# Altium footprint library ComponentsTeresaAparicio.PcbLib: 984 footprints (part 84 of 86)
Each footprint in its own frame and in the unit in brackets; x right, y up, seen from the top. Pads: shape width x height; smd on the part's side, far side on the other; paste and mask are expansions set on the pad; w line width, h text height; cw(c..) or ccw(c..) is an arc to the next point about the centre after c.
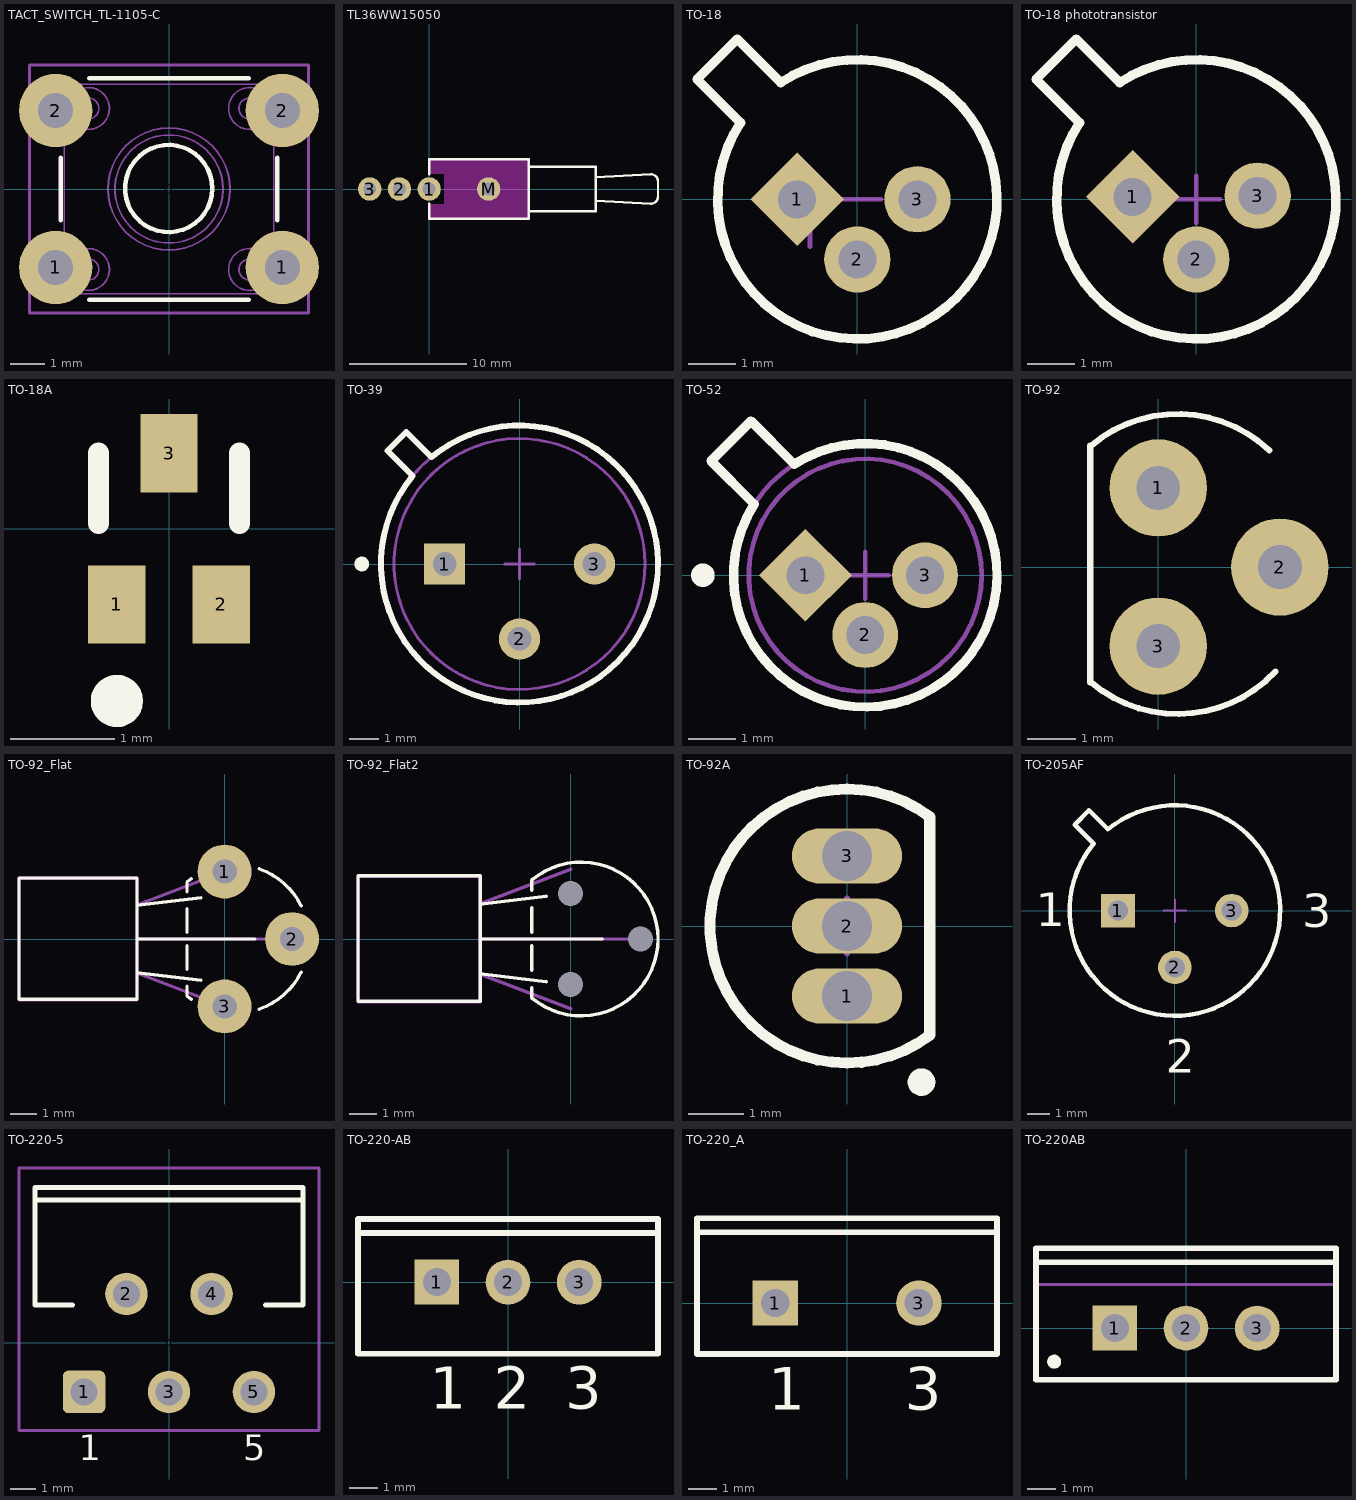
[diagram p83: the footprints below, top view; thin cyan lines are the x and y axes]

## TACT_SWITCH_TL-1105-C [mm] "E-Switch TL1105 series tact switch 8.0mm stem height"
height 8
pads (5):
  round 0.508 on Mech14: 0(0,0)
  round 2.1 hole 1: 1(-3.25,-2.25) 1(3.25,-2.25) 2(-3.25,2.25) 2(3.25,2.25)
Top Overlay:
  circle w0.127: c-0.011,0.014 r1.25
  lines w0.127: -3.1,-0.9 -3.1,0.9 ; -2.286,-3.175 2.286,-3.175 ; -2.286,3.175 2.286,3.175 ; 3.1,-0.9 3.1,0.9
Mechanical 13:
  circle w0.05: c-2.309,-2.309 r0.6
  circle w0.05: c2.309,-2.309 r0.6
  circle w0.05: c-2.309,2.309 r0.6
  circle w0.05: c2.309,2.309 r0.6
  circle w0.05: c2.307,-2.308 r0.3
  circle w0.05: c-2.31,-2.308 r0.3
  circle w0.05: c2.307,2.309 r0.3
  circle w0.05: c-2.31,2.309 r0.3
  circle w0.05: c0,0 r1.75
  circle w0.05: c0,0 r1.55
  lines w0.05: -3.886,-2.65 -3.886,-1.85 ; -3.886,1.85 -3.886,2.65 ; -3.3,-2.65 -3.3,-1.85 ; -3.3,1.85 -3.3,2.65 ; -3.15,-2.65 -3.15,-1.85 ; -3.15,1.85 -3.15,2.65 ; -3,-2.65 -3.95,-2.65 -3.95,-1.85 -3,-1.85 ; -3,1.85 -3.95,1.85 -3.95,2.65 -3,2.65 ; -2.561,-2.853 ccw(c-2.309,-2.309) -2.538,-2.863 ; -2.561,1.764 ccw(c-2.309,2.309) -2.538,1.754 ; 2.056,-2.853 ccw(c2.309,-2.309) 2.079,-2.863 ; 2.056,1.764 ccw(c2.309,2.309) 2.079,1.754 ; 3,-2.65 3.95,-2.65 3.95,-1.85 3,-1.85 ; 3,1.85 3.95,1.85 3.95,2.65 3,2.65 ; 3.15,-2.65 3.15,-1.85 ; 3.15,1.85 3.15,2.65 ; 3.3,-2.65 3.3,-1.85 ; 3.3,1.85 3.3,2.65 ; 3.886,-2.65 3.886,-1.85 ; 3.886,1.85 3.886,2.65 ; -3,-3 3,-3 3,3 -3,3 -3,-3
Mechanical 14:
  lines w0.076: -4,-3.556 4,-3.556 4,3.556 -4,3.556 -4,-3.556
3D body: height 8, standoff -3.5, extent -3.95,-3 3.95,3

## TL36WW15050 [mm] "Switch; 4 Leads"
pads (4):
  round 2 hole 1.1: 1(0,0) 2(-2.54,0) 3(-5.08,0) M(5.08,0)
Top Layer keep-out:
  region: 0,-1.27 0,-2.54 1.27,-2.54 1.27,-1.27
  region: 0,2.54 0,1.27 1.27,1.27 1.27,2.54
  region: 1.27,2.54 1.27,-2.54 8.509,-2.54 8.509,2.54
Top Overlay:
  lines w0.2: 0,-1.27 0,-2.54 8.509,-2.54 8.509,2.54 0,2.54 0,1.27 ; 8.509,-1.905 14.224,-1.905 14.224,1.905 8.509,1.905 ; 14.224,-1.016 18.923,-1.27 ccw(c18.923,-0.635) 19.558,-0.635 19.558,0.635 ccw(c18.923,0.635) 18.923,1.27 14.224,1.016

## TO-18 [mm] "Can; 3 Leads; Pin Circle Dia. 2.54 mm; Lead Dia. 0.48 mm (max)"
height 5.33
pads (3):
  rect 1.4x1.4 hole 0.8 rot 45: 1(-1.27,0)
  round 1.4 hole 0.8: 2(0,-1.27) 3(1.27,0)
Top Overlay:
  lines w0.2: -3.386,2.537 -2.467,1.618 ccw(c0,0) -1.618,2.467 -2.537,3.386 -3.386,2.537
Mechanical 15:
  lines w0.1: -1,-1 -1,0 ; -0.5,0 0.5,0
3D body: height 2.67, standoff -5.66, extent -3,-2.982 2.982,3

## TO-18 phototransistor [mm] "Can; 3 Leads; Pin Circle Dia. 2.54 mm; Lead Dia. 0.48 mm (max)"
height 5.33
pads (3):
  rect 1.4x1.4 hole 0.8 rot 45: 1(-1.346,0.051)
  round 1.4 hole 0.8: 2(0,-1.27) 3(1.295,0.076)
Top Overlay:
  lines w0.2: -3.386,2.537 -2.467,1.618 ccw(c0,0) -1.618,2.467 -2.537,3.386 -3.386,2.537
Mechanical 15:
  lines w0.1: -0.5,0 0.5,0 ; 0,-0.5 0,0.5
3D body: height 13.95, standoff -2.05, extent -3.429,-3.429 3.429,3.429

## TO-18A [mm] "SC-89; 3 Flat Leads; Body 1.6 x 1.6 x 0.7 mm, inc leads (LxWxH typ)"
height 0.8
pads (3):
  rect 0.55x0.75 smd: 1(-0.5,-0.725) 2(0.5,-0.725) 3(0,0.725)
Top Overlay:
  circle w0.25: c-0.5,-1.65 r0.125
  lines w0.2: -0.676,0.05 -0.676,0.725 ; 0.675,0.05 0.675,0.725

## TO-39 [mm] "Can; 3 Leads; Pin Circle Dia. 5.08 mm; Lead Dia. 0.48 mm (max)"
height 4.55
pads (3):
  rect 1.4x1.4 hole 0.8: 1(-2.54,0)
  round 1.4 hole 0.8: 2(0,-2.54) 3(2.54,0)
Top Overlay:
  circle w0.25: c-5.35,0 r0.125
  lines w0.2: -3.626,2.99 -4.475,3.838 -3.838,4.475 -2.99,3.626 ; -3.622,2.987 ccw(c0,0) -2.987,3.622
Mechanical 13:
  circle w0.1: c0,0 r4.255
  circle w0.1: c0,0 r4.695
Mechanical 15:
  lines w0.1: -0.5,0 0.5,0 ; 0,-0.5 0,0.5
3D body: height 4.55, standoff 1.27, extent -4.264,-4.264 4.264,4.264
3D body: height 1.27, standoff 0, extent -4.705,-4.705 4.705,4.705

## TO-52 [mm] "Can; 3 Leads; Pin Circle Dia. 2.54 mm; Lead Dia. 0.48 mm (max)"
height 2.67
pads (3):
  rect 1.4x1.4 hole 0.8 rot 45: 1(-1.27,0)
  round 1.4 hole 0.8: 2(0,-1.27) 3(1.27,0)
Top Overlay:
  circle w0.25: c-3.45,0 r0.125
  lines w0.2: -3.277,2.429 -2.429,3.277 -1.51,2.358 cw(c0,0) -2.358,1.51 -3.277,2.429
Mechanical 13:
  circle w0.1: c0,0 r2.475
  circle w0.1: c0,0 r2.8
Mechanical 15:
  lines w0.1: -0.5,0 0.5,0 ; 0,-0.5 0,0.5
3D body: height 2.67, standoff 0.76, extent -2.486,-2.486 2.486,2.486
3D body: height 0.76, standoff 0, extent -2.808,-2.808 2.808,2.808

## TO-92 [mil]
height 397.64
pads (3):
  round 80 hole 36: 1(0,65) 2(100,0) 3(0,-65)
Top Overlay:
  lines w5: -55.86,-95 -55.86,100 ; -55,-95 ccw(c15.86,-10.55) 96.45,-85.77 ; -55,100 cw(c15.86,15.55) 91.25,95.98
3D body: height 404.72, standoff -100, extent -54.52,-94.57 107.49,94.56

## TO-92_Flat [mil]
height 151.57
pads (3):
  round 80 hole 36: 1(0,100) 2(100,0) 3(0,-100)
Top Overlay:
  lines w5: -130.03,0 45,0 ; -130,-50 -35.14,-61.16 ; -130,50 -35.14,61.16 ; -55.86,-70 -55.86,-84.45 ccw(c15,0) -49.54,-89.37 ; -55.86,-45 -55.86,-10 ; -55.86,10 -55.86,45 ; -55.86,70 -55.86,84.45 cw(c15,0) -49.54,89.37 ; 51.42,-104.05 ccw(c15,0) 113.6,-49.3 ; 51.42,104.05 cw(c15,0) 113.6,49.3 ; -305.03,-89.45 -305.03,90.55 -130.03,90.55 -130.03,-89.45 -305.03,-89.45
Mechanical 13:
  lines w5: -130,-50.44 0,-100 ; -130,0.1 100,0 ; -130,50.44 0,100 ; -305,-90 -305,90 -130,90 -130,-90 -305,-90
3D body: height 141.73, standoff -100, extent -307.08,-109.84 109.85,109.85

## TO-92_Flat2 [mil]
height 151.57
pads (3):
  round 0 / inner round 0 / far side round 80 hole 36 unplated: 1(0,65) 2(100,0) 3(0,-65)
Top Overlay:
  lines w5: -130.03,0 45,0 ; -130,-50 -35.14,-61.16 ; -130,50 -35.14,61.16 ; -55.86,-70 -55.86,-84.45 ccw(c15,0) -55.86,84.45 -55.86,70 ; -55.86,-45 -55.86,-10 ; -55.86,10 -55.86,45 ; -305.03,-89.45 -130.03,-89.45 -130.03,90.55 -305.03,90.55 -305.03,-89.45
Mechanical 13:
  lines w5: -130,-50.44 0,-100 ; -130,0.1 100,0 ; -130,50.44 0,100 ; -305,-90 -130,-90 -130,90 -305,90 -305,-90
3D body: height 141.73, standoff -100, extent -307.08,-94.48 109.85,94.5

## TO-92A [mm] "TO, Flat Index; 3 In-Line, Axial Leads; Body Dia. 4.5mm; Leads 0.51 x 0.48 mm (max)"
height 6.86
pads (3):
  oval 2x1 hole 0.9: 1(0,-1.27) 2(0,0) 3(0,1.27)
Top Overlay:
  circle w0.25: c1.35,-2.83 r0.125
  lines w0.2: 1.5,-1.98 cw(c0,0) 1.5,1.98 1.5,-1.98
Mechanical 13:
  lines w0.1: 1.5,-1.98 cw(c0,0) 1.5,1.98 1.5,-1.98
Mechanical 15:
  lines w0.1: -0.5,0 0.5,0 ; 0,-0.5 0,0.5
3D body: height 6.86, standoff 2.2, extent -2.497,-2.497 1.501,2.497

## TO-205AF [mm] "Can; 3 Leads; Pin Circle Dia. 5.08 mm; Lead Dia. 0.53 mm (max)"
height 4.57
pads (3):
  rect 1.5x1.5 hole 0.9: 1(-2.54,0)
  round 1.5 hole 0.9: 2(0,-2.54) 3(2.54,0)
Top Overlay:
  lines w0.2: -4.475,3.838 -3.838,4.475 -2.99,3.626 cw(c0,0) -3.626,2.99 -4.475,3.838
  text "3" at 5.694,-0.751 h1.5
  text "2" at -0.415,-7.238 h1.5
  text "1" at -6.201,-0.697 h1.5
Mechanical 15:
  lines w0.1: -0.5,0 0.5,0 ; 0,-0.5 0,0.5

## TO-220-5 [mm] "TO, Thru-Hole, Vertical, Heatsink Mounted; 5 Bent Staggered Leads; Pitch 1.7mm"
height 21.1
pads (6):
  round 0.5 on Mech14: 0(0,0)
  rrect25% 1.7x1.7 hole 1.092: 1(-3.4,-1.96)
  round 1.7 hole 1.092: 2(-1.7,1.96) 3(0,-1.96) 4(1.7,1.96) 5(3.4,-1.96)
Top Overlay:
  lines w0.2: -5.35,5.71 5.35,5.71 ; -3.854,1.51 -5.35,1.51 -5.35,6.21 5.35,6.21 5.35,1.51 3.854,1.51
  text "1" at -3.62,-4.685 h1.02
  text "5" at 2.98,-4.685 h1.02
Mechanical 14:
  lines w0.127: -6,-3.5 -6,7 6,7 6,-3.5 -6,-3.5
3D body: height 20.99, standoff -3, extent -5.08,-2.16 5.08,6.08

## TO-220-AB [mm] "TO, Thru-Hole, Vertical, Heatsink Mounted; 3 In-Line Leads; Pitch 2.54 mm"
height 19.1
pads (3):
  rect 1.6x1.6 hole 1: 1(-2.54,0)
  round 1.6 hole 1: 2(0,0) 3(2.54,0)
Top Overlay:
  lines w0.2: -5.35,1.75 5.35,1.75 ; -5.35,-2.55 -5.35,2.25 5.35,2.25 5.35,-2.55 -5.35,-2.55
  text "3" at 2.04,-4.525 h1.5
  text "2" at -0.5,-4.525 h1.5
  text "1" at -2.79,-4.525 h1.5

## TO-220_A [mm] "TO, Thru-Hole, Vertical, Heatsink Mounted; 3 In-Line Leads (1 Absent); Pitch 2.54 mm"
height 19.3
pads (2):
  rect 1.6x1.6 hole 1: 1(-2.54,0)
  round 1.6 hole 1: 3(2.54,0)
Top Overlay:
  lines w0.2: -5.3,2.5 5.3,2.5 ; -5.3,-1.8 -5.3,3 5.3,3 5.3,-1.8 -5.3,-1.8
  text "1" at -2.79,-3.775 h1.5
  text "3" at 2.04,-3.775 h1.5

## TO-220AB [mm] "TO, Thru-Hole, Vertical, Heatsink Mounted; 3 In-Line Leads; Pitch 2.54 mm"
height 19.3
pads (3):
  rect 1.6x1.6 hole 1: 1(-2.54,0)
  round 1.6 hole 1: 2(0,0) 3(2.54,0)
Top Overlay:
  circle w0.25: c-4.7,-1.2 r0.125
  lines w0.2: -5.35,2.35 5.35,2.35 ; -5.35,-1.85 5.35,-1.85 5.35,2.85 -5.35,2.85 -5.35,-1.85
Mechanical 13:
  lines w0.1: -5.35,1.55 5.35,1.55 ; -5.35,-1.85 -5.35,2.85 5.35,2.85 5.35,-1.85 -5.35,-1.85
Mechanical 15:
  lines w0.1: -0.5,0 0.5,0 ; 0,-0.5 0,0.5
3D body: height 19.3, standoff 12.9, extent -5.349,1.551 5.349,2.849
3D body: height 12.9, standoff 4, extent -5.4,-1.9 5.4,2.9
